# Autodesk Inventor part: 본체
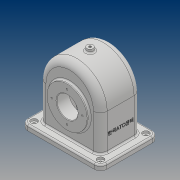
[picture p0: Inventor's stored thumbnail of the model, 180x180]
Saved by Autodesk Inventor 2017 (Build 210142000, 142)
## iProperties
Part Number: 본체
Material: 일반
Document SubType Name: Modeling
Designer: 20
Density: 1 g/cm^3
Appearance: 기본값
Author: 20
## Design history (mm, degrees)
sketch "스케치5"
  geometry: L1 (58, 13)-(58, -65); L2 (58, -65)-(-58, -65); L3 (-58, -65)-(-58, 13); A1 r 58 centre (0, 13) between (58, 13) and (-58, 13); 1 further point
  constraints: 6 end point, 2 point on circle, 2 tangent, 2 vertical, 1 centre point, 1 horizontal, 1 vertical alignment
  dimensions: "d13" = 116 diameter of A1; "d14" = 13 distance of point (0, 0) A1.centre; "d15" = 78 distance from line of L2 A1.centre
extrude "돌출4" new body sketch "스케치5" stored distance "d16" = 77; taper "d17" = 0 deg
sketch "스케치6"
  geometry: L1 (58, -65)-(58, 13) reference; L2 (-58, 13)-(-58, -65) reference; L3 (-52, -78)-(-52, 13); L4 (52, 13)-(52, -78); L5 (52, -78)-(-52, -78); A1 r 58 centre (0, 13) between (58, 13) and (-58, 13) reference; A2 r 52 centre (0, 13) between (52, 13) and (-52, 13); 1 further point
  constraints: 6 end point, 2 point on circle, 1 centre point, 1 horizontal, 2 other
  dimensions: "d18" = 6 radial gap between concentric circles of A1 A2; "d19" = 78 distance from line of L5 point (0, 0)
extrude "돌출5" cut sketch "스케치6" stored distance "d20" = 67; taper "d21" = 0 deg
sketch "스케치7"
  geometry: L1 (6, -72)-(6, -5) reference; L2 (110, -72)-(6, -72) reference; L3 (6, -5)-(110, -5) reference; L4 (110, -5)-(110, -72) reference; L5 (133, -93.5)-(-17, -93.5); L6 (-17, -93.5)-(-17, 16.5); L7 (-17, 16.5)-(133, 16.5); L8 (133, 16.5)-(133, -93.5); L9 (133, -93.5)-(-17, 16.5); L10 (-17, -93.5)-(133, 16.5); 1 further point
  constraints: 12 end point, 2 midpoint, 2 parallel, 1 horizontal, 1 perpendicular
  dimensions: "d22" = 110 distance of L5.end L6.end; "d23" = 150 distance of L6.end L7.end
extrude "돌출6" join sketch "스케치7" distance "d24" = 10; taper "d25" = 0 deg
sketch "스케치8"
  geometry: C1 r 38 at (0, 0); 1 further point
  constraints: 1 centre point, 1 coincident
  dimensions: "d26" = 76 diameter of C1
extrude "돌출7" join sketch "스케치8" distance "d27" = 10; taper "d28" = 0 deg
sketch "스케치10"
  geometry: C1 r 38 at (0, 0); 1 further point
  constraints: 1 centre point, 1 coincident
  dimensions: "d29" = 76 diameter of C1
extrude "돌출8" join sketch "스케치10" distance "d30" = 5; taper "d31" = 0 deg
sketch "스케치11"
  geometry: C1 r 28 at (0, 0); 1 further point
  constraints: 1 centre point, 1 coincident
  dimensions: "d32" = 56 diameter of C1
extrude "돌출9" join sketch "스케치11" distance "d33" = 14; taper "d34" = 0 deg
sketch "스케치13"
  geometry: 1 further point
feature "면 기울기1" dims angle "d35" = 40 deg
sketch "스케치15"
  geometry: C1 r 20 at (0, 0); 1 further point
  constraints: 1 centre point, 1 coincident
  dimensions: "d36" = 40 diameter of C1
extrude "돌출10" cut sketch "스케치15" distance "d37" = 500; taper "d38" = 0 deg
sketch "스케치17"
  geometry: 2 further points
  constraints: 1 vertical alignment
  dimensions: "d39" = 29 distance of point (0, 0) point (0, 29)
hole "구멍1" sketch "스케치17" at (0, 29) diameter "d40" = 3.242; stored, may be unused: countersink angle "d44" = 90 deg, drill point angle "d46" = 118 deg; dims "d41" = 8, "d42" = 4, "d43" = 2, "d45" = 10
sketch "스케치18"
  geometry: 2 further points
  constraints: 1 vertical alignment
  dimensions: "d50" = 29 distance of point (0, 0) point (0, -29)
hole "구멍2" sketch "스케치18" at (0, -29) diameter "d51" = 3.242; stored, may be unused: countersink angle "d55" = 90 deg, drill point angle "d57" = 118 deg; dims "d52" = 8, "d53" = 4, "d54" = 2, "d56" = 10
node "작업 평면1"
sketch "스케치19"
  geometry: C1 r 6 at (75, 55); 1 further point
  constraints: 1 centre point, 1 coincident
  dimensions: "d62" = 12 diameter of C1
extrude "돌출11" join sketch "스케치19" stored distance "d63" = 500; taper "d64" = 5 deg
hole "구멍3" diameter "d67" = 4.459; stored, may be unused: countersink angle "d71" = 90 deg, drill point angle "d73" = 0 deg; dims "d65" = 10, "d66" = 10, "d68" = 10, "d69" = 4, "d70" = 2, "d72" = 30
fillet "모깎기1" dims "d74" = 12
hole "구멍4" diameter "d77" = 5; stored, may be unused: countersink angle "d81" = 90 deg, drill point angle "d83" = 0 deg; dims "d75" = 10, "d76" = 10, "d78" = 10, "d79" = 12, "d80" = 4, "d82" = 30
sketch "스케치21"
  geometry: L1 (68, 0)-(0, 0) reference; L2 (78, -4.5)-(78, 81.5) reference; 2 further points
  constraints: 1 other
  dimensions: "d90" = 38.5 distance from line of L1 point (38, 38.5); "d91" = 40 distance from line of L2 point (38, 38.5)
feature "엠보싱1" sketch "스케치21" dims "d92" = 0.5, "d93" = 0
chamfer "모따기1" distance "d94" = 1; stored, may be unused: second distance "d95" = 2, angle "d96" = 45 deg
fillet "모깎기2" dims "d97" = 8
fillet "모깎기3" dims "d98" = 3
fillet "모깎기4" dims "d99" = 3
fillet "모깎기5" dims "d100" = 13
fillet "모깎기6" dims "d101" = 3
fillet "모깎기7" dims "d102" = 3
fillet "모깎기8" dims "d103" = 3
node "솔리드2"
pattern_circular "원형 패턴1" dims angle "d48" = 360 deg
pattern_circular "원형 패턴2" dims angle "d59" = 360 deg
pattern_linear "직사각형 패턴1" dims "d86" = 126, "d89" = 86
other parameters: "d61" = -142
